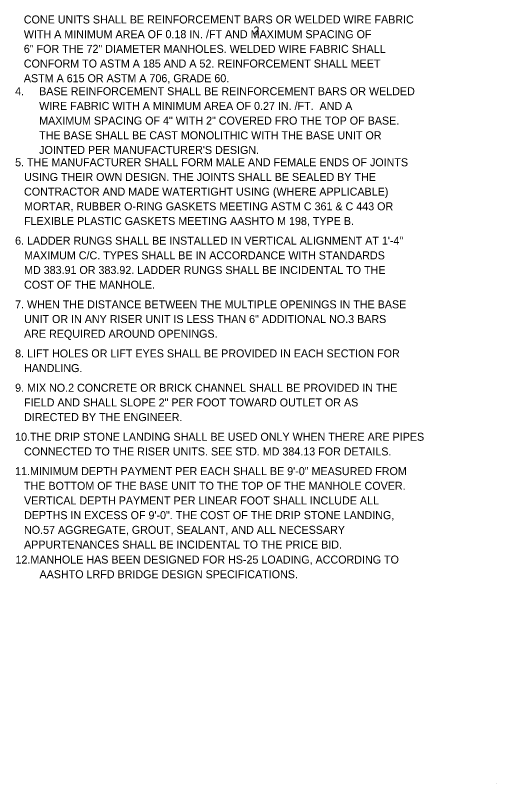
# Model space of a CAD drawing. Extents: x 1.8 to 9.1, y -6 to 4.
# Drawn here: x 5.51 to 9.11, y -6.01 to -0.26 of the extents above; entities that cross this region are included whole.
import ezdxf

# ---------------------------------------------------------------- set-up
doc = ezdxf.new("R2010")
doc.units = 0
doc.layers.add('DETL-NOTE', color=7, linetype='Continuous')
doc.layers.add('TTLB-TEXT', color=7, linetype='Continuous')

msp = doc.modelspace()

# ---------------------------------------------------------------- linework, layer by layer
at = {"layer": 'TTLB-TEXT'}
msp.add_line((9.1094, -6.0118), (9.1094, -6.0118), dxfattribs=at)

# ---------------------------------------------------------------- texts
at = {"layer": 'DETL-NOTE'}
for s, height, p in [('   CONE UNITS SHALL BE REINFORCEMENT BARS OR WELDED WIRE FABRIC', 0.05998, (5.5033, -0.3175)), ('2', 0.06, (7.2891, -0.3998)), ('   WITH A MINIMUM AREA OF 0.18 IN. /FT AND MAXIMUM SPACING OF ', 0.05998, (5.5033, -0.4275)), ('   6" FOR THE 72" DIAMETER MANHOLES. WELDED WIRE FABRIC SHALL ', 0.05998, (5.5033, -0.5374)), ('   CONFORM TO ASTM A 185 AND A 52. REINFORCEMENT SHALL MEET ', 0.05998, (5.5033, -0.6474)), ('   ASTM A 615 OR ASTM A 706, GRADE 60.', 0.05998, (5.5033, -0.7574)), ('4.', 0.05998, (5.5051, -0.8549)), ('BASE REINFORCEMENT SHALL BE REINFORCEMENT BARS OR WELDED ', 0.05998, (5.685, -0.8549)), ('WIRE FABRIC WITH A MINIMUM AREA OF 0.27 IN. /FT.  AND A ', 0.05998, (5.685, -0.9649)), ('MAXIMUM SPACING OF 4" WITH 2" COVERED FRO THE TOP OF BASE. ', 0.05998, (5.685, -1.0748)), ('THE BASE SHALL BE CAST MONOLITHIC WITH THE BASE UNIT OR ', 0.05998, (5.685, -1.1848)), ("JOINTED PER MANUFACTURER'S DESIGN.", 0.05998, (5.685, -1.2948)), ('5. THE MANUFACTURER SHALL FORM MALE AND FEMALE ENDS OF JOINTS', 0.05998, (5.5051, -1.3871)), ('   USING THEIR OWN DESIGN. THE JOINTS SHALL BE SEALED BY THE', 0.05998, (5.5051, -1.4971)), ('   CONTRACTOR AND MADE WATERTIGHT USING (WHERE APPLICABLE)', 0.05998, (5.5051, -1.607)), ('   MORTAR, RUBBER O-RING GASKETS MEETING ASTM C 361 & C 443 OR', 0.05998, (5.5051, -1.717)), ('   FLEXIBLE PLASTIC GASKETS MEETING AASHTO M 198, TYPE B.', 0.05998, (5.5051, -1.827)), ('6. LADDER RUNGS SHALL BE INSTALLED IN VERTICAL ALIGNMENT AT 1\'-4"', 0.05998, (5.505, -1.9743)), ('   MAXIMUM C/C. TYPES SHALL BE IN ACCORDANCE WITH STANDARDS', 0.05998, (5.505, -2.0842)), ('   MD 383.91 OR 383.92. LADDER RUNGS SHALL BE INCIDENTAL TO THE ', 0.05998, (5.505, -2.1942)), ('   COST OF THE MANHOLE.', 0.05998, (5.505, -2.3042)), ('7. WHEN THE DISTANCE BETWEEN THE MULTIPLE OPENINGS IN THE BASE', 0.05998, (5.505, -2.4515)), ('   UNIT OR IN ANY RISER UNIT IS LESS THAN 6" ADDITIONAL NO.3 BARS', 0.05998, (5.505, -2.5615)), ('   ARE REQUIRED AROUND OPENINGS.', 0.05998, (5.505, -2.6715)), ('8. LIFT HOLES OR LIFT EYES SHALL BE PROVIDED IN EACH SECTION FOR', 0.05998, (5.505, -2.8188)), ('   HANDLING.', 0.05998, (5.505, -2.9288)), ('9. MIX NO.2 CONCRETE OR BRICK CHANNEL SHALL BE PROVIDED IN THE', 0.05998, (5.505, -3.0761)), ('   FIELD AND SHALL SLOPE 2" PER FOOT TOWARD OUTLET OR AS', 0.05998, (5.505, -3.1861)), ('   DIRECTED BY THE ENGINEER.', 0.05998, (5.505, -3.296)), ('10.THE DRIP STONE LANDING SHALL BE USED ONLY WHEN THERE ARE PIPES', 0.05998, (5.505, -3.4434)), ('   CONNECTED TO THE RISER UNITS. SEE STD. MD 384.13 FOR DETAILS.', 0.05998, (5.505, -3.5533)), ('11.MINIMUM DEPTH PAYMENT PER EACH SHALL BE 9\'-0" MEASURED FROM', 0.05998, (5.505, -3.7007)), ('   THE BOTTOM OF THE BASE UNIT TO THE TOP OF THE MANHOLE COVER.', 0.05998, (5.505, -3.8106)), ('   VERTICAL DEPTH PAYMENT PER LINEAR FOOT SHALL INCLUDE ALL', 0.05998, (5.505, -3.9206)), ('   DEPTHS IN EXCESS OF 9\'-0". THE COST OF THE DRIP STONE LANDING,', 0.05998, (5.505, -4.0306)), ('   NO.57 AGGREGATE, GROUT, SEALANT, AND ALL NECESSARY', 0.05998, (5.505, -4.1406)), ('   APPURTENANCES SHALL BE INCIDENTAL TO THE PRICE BID.', 0.05998, (5.505, -4.2505)), ('12.MANHOLE HAS BEEN DESIGNED FOR HS-25 LOADING, ACCORDING TO ', 0.05998, (5.5077, -4.3632)), ('AASHTO LRFD BRIDGE DESIGN SPECIFICATIONS.', 0.05998, (5.6877, -4.4732))]:
    msp.add_text(s, height=height, dxfattribs=at).set_placement(p)

doc.saveas('drawing.dxf')
